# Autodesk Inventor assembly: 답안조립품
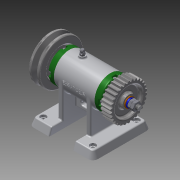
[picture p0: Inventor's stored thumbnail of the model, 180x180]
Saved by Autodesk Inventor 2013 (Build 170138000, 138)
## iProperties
Created: 2016-07
Part Number: 답안조립품
Document SubType Name: Assembly
Designer: WINDOWS7
Author: WINDOWS7
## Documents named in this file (16)
- C:\Users\WINDOWS7\Desktop\460708V1001\답안조립품.iam
- C:\Users\WINDOWS7\Desktop\460708V1001\1-본체.ipt
- C:\Users\WINDOWS7\Desktop\460708V1001\V벨트풀리.ipt
- C:\Users\WINDOWS7\Desktop\460708V1001\너트 M 8.ipt
- C:\Users\WINDOWS7\Desktop\460708V1001\니플 M 6 x 0.75.ipt
- C:\Users\WINDOWS7\Desktop\460708V1001\베어링 15 x 32 x 9.ipt
- C:\Users\WINDOWS7\Desktop\460708V1001\볼트 M 6 x 8.ipt
- C:\Users\WINDOWS7\Desktop\460708V1001\볼트 M4 x 12.ipt
- C:\Users\WINDOWS7\Desktop\460708V1001\스퍼기어.ipt
- C:\Users\WINDOWS7\Desktop\460708V1001\스프링와셔 8.ipt
- C:\Users\WINDOWS7\Desktop\460708V1001\오일 실 15 25 7.ipt
- C:\Users\WINDOWS7\Desktop\460708V1001\와셔 6x11.5.ipt
- C:\Users\WINDOWS7\Desktop\460708V1001\와셔 8x17.ipt
- C:\Users\WINDOWS7\Desktop\460708V1001\축.ipt
- C:\Users\WINDOWS7\Desktop\460708V1001\커버.ipt
- C:\Users\WINDOWS7\Desktop\460708V1001\키 3 x 3 x 12.ipt
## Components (12 placed, 4 different names)
1. 1-본체:1
2. V벨트풀리:1
3. KS B 2023 6002 - 15 x 32 x 9:1
4. KS B 2023 6002 - 15 x 32 x 9:2
5. ISO 4762 M4 x 12:1
6. ISO 4762 M4 x 12:3
7. ISO 4762 M4 x 12:4
8. ISO 4762 M4 x 12:5
9. ISO 4762 M4 x 12:2
10. ISO 4762 M4 x 12:6
11. ISO 4762 M4 x 12:7
12. ISO 4762 M4 x 12:8
